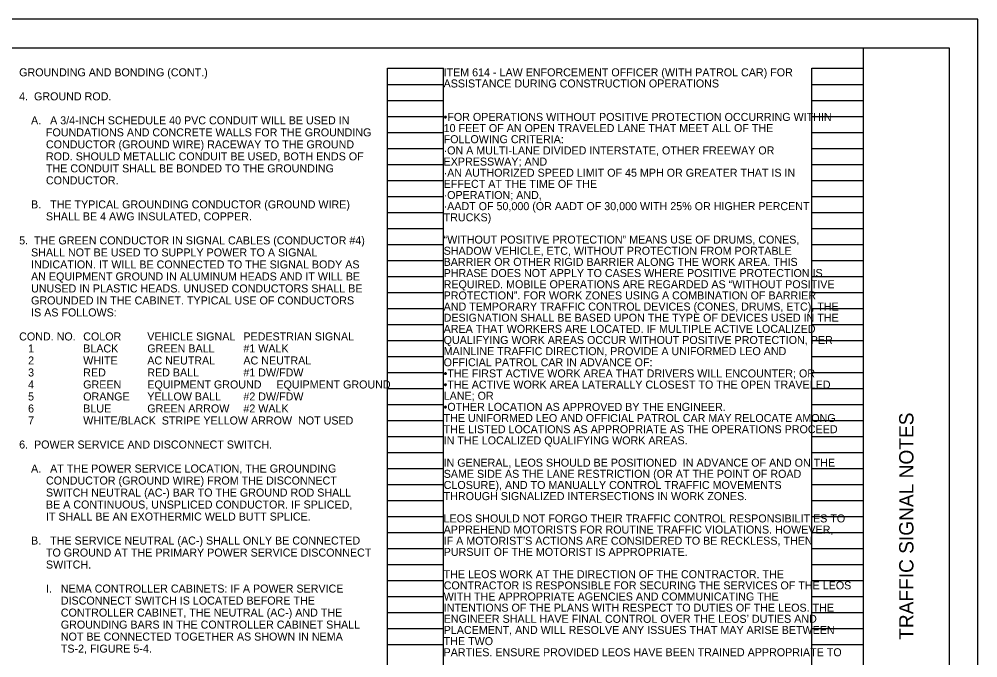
# Model space of a CAD drawing. Extents: x 0 to 34, y 0 to 22.
# Drawn here: x 17.24 to 34, y 10.83 to 22 of the extents above; entities that cross this region are included whole.
import ezdxf

# ---------------------------------------------------------------- set-up
doc = ezdxf.new("R2010")
doc.units = 0
for name, color, linetype in [('SH_Border', 7, 'Continuous'), ('SH_Cut_Line', 7, 'Continuous'), ('SH_Data', 7, 'Continuous'), ('SH_Text', 7, 'Continuous')]:
    doc.layers.add(name, color=color, linetype=linetype)

msp = doc.modelspace()

# ---------------------------------------------------------------- linework, layer by layer
at = {"layer": 'SH_Border'}
msp.add_line((32, 0.5), (32, 21.5), dxfattribs=at)
msp.add_lwpolyline([(1.5, 21.5), (33.5, 21.5), (33.5, 0.5), (1.5, 0.5)], close=True, dxfattribs=at)
at = {"layer": 'SH_Cut_Line'}
msp.add_lwpolyline([(0, 0), (34, 0), (34, 22), (0, 22)], close=True, dxfattribs=at)
at = {"layer": 'SH_Data'}
for p, q in [((23.68, 0.98), (23.68, 21.14)), ((23.68, 21.14), (24.66, 21.14)), ((24.66, 0.98), (24.66, 21.14)), ((31.1, 0.98), (31.1, 21.14)), ((31.1, 21.14), (32, 21.14)), ((32, 0.98), (32, 21.14)), ((23.68, 20.86), (24.66, 20.86)), ((31.1, 20.86), (32, 20.86)), ((23.68, 20.58), (24.66, 20.58)), ((31.1, 20.58), (32, 20.58)), ((23.68, 20.3), (24.66, 20.3)), ((31.1, 20.3), (32, 20.3)), ((23.68, 20.02), (24.66, 20.02)), ((31.1, 20.02), (32, 20.02)), ((23.68, 19.74), (24.66, 19.74)), ((31.1, 19.74), (32, 19.74)), ((23.68, 19.46), (24.66, 19.46)), ((31.1, 19.46), (32, 19.46)), ((23.68, 19.18), (24.66, 19.18)), ((31.1, 19.18), (32, 19.18)), ((23.68, 18.9), (24.66, 18.9)), ((31.1, 18.9), (32, 18.9)), ((23.68, 18.62), (24.66, 18.62)), ((31.1, 18.62), (32, 18.62)), ((23.68, 18.34), (24.66, 18.34)), ((31.1, 18.34), (32, 18.34)), ((23.68, 18.06), (24.66, 18.06)), ((31.1, 18.06), (32, 18.06)), ((23.68, 17.78), (24.66, 17.78)), ((31.1, 17.78), (32, 17.78)), ((23.68, 17.5), (24.66, 17.5)), ((31.1, 17.5), (32, 17.5)), ((23.68, 17.22), (24.66, 17.22)), ((31.1, 17.22), (32, 17.22)), ((23.68, 16.94), (24.66, 16.94)), ((31.1, 16.94), (32, 16.94)), ((23.68, 16.66), (24.66, 16.66)), ((31.1, 16.66), (32, 16.66)), ((23.68, 16.38), (24.66, 16.38)), ((31.1, 16.38), (32, 16.38)), ((23.68, 16.1), (24.66, 16.1)), ((31.1, 16.1), (32, 16.1)), ((23.68, 15.82), (24.66, 15.82)), ((31.1, 15.82), (32, 15.82)), ((23.68, 15.54), (24.66, 15.54)), ((31.1, 15.54), (32, 15.54)), ((23.68, 15.26), (24.66, 15.26)), ((31.1, 15.26), (32, 15.26)), ((23.68, 14.98), (24.66, 14.98)), ((31.1, 14.98), (32, 14.98)), ((23.68, 14.7), (24.66, 14.7)), ((31.1, 14.7), (32, 14.7)), ((23.68, 14.42), (24.66, 14.42)), ((31.1, 14.42), (32, 14.42)), ((23.68, 14.14), (24.66, 14.14)), ((31.1, 14.14), (32, 14.14)), ((23.68, 13.86), (24.66, 13.86)), ((31.1, 13.86), (32, 13.86)), ((23.68, 13.58), (24.66, 13.58)), ((31.1, 13.58), (32, 13.58)), ((23.68, 13.3), (24.66, 13.3)), ((31.1, 13.3), (32, 13.3)), ((23.68, 13.02), (24.66, 13.02)), ((31.1, 13.02), (32, 13.02)), ((23.68, 12.74), (24.66, 12.74)), ((31.1, 12.74), (32, 12.74)), ((23.68, 12.46), (24.66, 12.46)), ((31.1, 12.46), (32, 12.46)), ((23.68, 12.18), (24.66, 12.18)), ((31.1, 12.18), (32, 12.18)), ((23.68, 11.9), (24.66, 11.9)), ((31.1, 11.9), (32, 11.9)), ((23.68, 11.62), (24.66, 11.62)), ((31.1, 11.62), (32, 11.62)), ((23.68, 11.34), (24.66, 11.34)), ((31.1, 11.34), (32, 11.34)), ((23.68, 11.06), (24.66, 11.06)), ((31.1, 11.06), (32, 11.06))]:
    msp.add_line(p, q, dxfattribs=at)

# ---------------------------------------------------------------- texts
msp.add_text('TRAFFIC SIGNAL NOTES', height=0.25, rotation=90, dxfattribs=at).set_placement((32.875, 11.144))
at = {"layer": 'SH_Text'}
for s, p in [('GROUNDING AND BONDING (CONT.)', (17.24, 21)), ('ITEM 614 - LAW ENFORCEMENT OFFICER (WITH PATROL CAR) FOR ', (24.66, 21)), ('ASSISTANCE DURING CONSTRUCTION OPERATIONS', (24.66, 20.805)), ('4.  GROUND ROD.', (17.24, 20.58)), ('    A.   A 3/4-INCH SCHEDULE 40 PVC CONDUIT WILL BE USED IN', (17.24, 20.16)), ('•FOR OPERATIONS WITHOUT POSITIVE PROTECTION OCCURRING WITHIN ', (24.66, 20.22)), ('10 FEET OF AN OPEN TRAVELED LANE THAT MEET ALL OF THE ', (24.661, 20.025)), ('         FOUNDATIONS AND CONCRETE WALLS FOR THE GROUNDING', (17.24, 19.95)), ('FOLLOWING CRITERIA:', (24.661, 19.83)), ('         CONDUCTOR (GROUND WIRE) RACEWAY TO THE GROUND', (17.24, 19.74)), ('         ROD. SHOULD METALLIC CONDUIT BE USED, BOTH ENDS OF', (17.24, 19.53)), ('·ON A MULTI-LANE DIVIDED INTERSTATE, OTHER FREEWAY OR ', (24.66, 19.634)), ('         THE CONDUIT SHALL BE BONDED TO THE GROUNDING', (17.24, 19.32)), ('EXPRESSWAY; AND', (24.66, 19.439)), ('·AN AUTHORIZED SPEED LIMIT OF 45 MPH OR GREATER THAT IS IN ', (24.66, 19.244)), ('         CONDUCTOR.', (17.24, 19.11)), ('EFFECT AT THE TIME OF THE', (24.661, 19.049)), ('·OPERATION; AND,', (24.66, 18.854)), ('    B.   THE TYPICAL GROUNDING CONDUCTOR (GROUND WIRE)', (17.24, 18.69)), ('·AADT OF 50,000 (OR AADT OF 30,000 WITH 25% OR HIGHER PERCENT ', (24.66, 18.659)), ('         SHALL BE 4 AWG INSULATED, COPPER.', (17.24, 18.48)), ('TRUCKS)', (24.661, 18.464)), ('5.  THE GREEN CONDUCTOR IN SIGNAL CABLES (CONDUCTOR #4)', (17.24, 18.06)), ('“WITHOUT POSITIVE PROTECTION” MEANS USE OF DRUMS, CONES, ', (24.66, 18.074)), ('    SHALL NOT BE USED TO SUPPLY POWER TO A SIGNAL', (17.24, 17.85)), ('SHADOW VEHICLE, ETC, WITHOUT PROTECTION FROM PORTABLE ', (24.661, 17.879)), ('    INDICATION. IT WILL BE CONNECTED TO THE SIGNAL BODY AS', (17.24, 17.64)), ('BARRIER OR OTHER RIGID BARRIER ALONG THE WORK AREA. THIS ', (24.661, 17.684)), ('PHRASE DOES NOT APPLY TO CASES WHERE POSITIVE PROTECTION IS ', (24.661, 17.489)), ('    AN EQUIPMENT GROUND IN ALUMINUM HEADS AND IT WILL BE', (17.24, 17.43)), ('REQUIRED. MOBILE OPERATIONS ARE REGARDED AS “WITHOUT POSITIVE ', (24.661, 17.293)), ('    UNUSED IN PLASTIC HEADS. UNUSED CONDUCTORS SHALL BE', (17.24, 17.22)), ('    GROUNDED IN THE CABINET. TYPICAL USE OF CONDUCTORS', (17.24, 17.01)), ('PROTECTION”. FOR WORK ZONES USING A COMBINATION OF BARRIER ', (24.661, 17.098)), ('    IS AS FOLLOWS:', (17.24, 16.8)), ('AND TEMPORARY TRAFFIC CONTROL DEVICES (CONES, DRUMS, ETC), THE ', (24.661, 16.903)), ('DESIGNATION SHALL BE BASED UPON THE TYPE OF DEVICES USED IN THE ', (24.661, 16.708)), ('AREA THAT WORKERS ARE LOCATED. IF MULTIPLE ACTIVE LOCALIZED ', (24.661, 16.513)), ('COND. NO.', (17.24, 16.38)), ('COLOR', (18.36, 16.38)), ('VEHICLE SIGNAL', (19.48, 16.38)), ('PEDESTRIAN SIGNAL', (21.16, 16.38)), ('QUALIFYING WORK AREAS OCCUR WITHOUT POSITIVE PROTECTION, PER ', (24.661, 16.318)), ('   1         ', (17.24, 16.17)), ('BLACK        ', (18.36, 16.17)), ('GREEN BALL      ', (19.48, 16.17)), ('#1 WALK', (21.16, 16.17)), ('MAINLINE TRAFFIC DIRECTION, PROVIDE A UNIFORMED LEO AND ', (24.661, 16.123)), ('   2         ', (17.24, 15.96)), ('WHITE        ', (18.36, 15.96)), ('AC NEUTRAL     ', (19.48, 15.96)), ('AC NEUTRAL', (21.16, 15.96)), ('OFFICIAL PATROL CAR IN ADVANCE OF:', (24.661, 15.928)), ('   3         ', (17.24, 15.75)), ('RED          ', (18.36, 15.75)), ('RED BALL         ', (19.48, 15.75)), ('#1 DW/FDW', (21.16, 15.75)), ('•THE FIRST ACTIVE WORK AREA THAT DRIVERS WILL ENCOUNTER; OR', (24.66, 15.733)), ('   4         ', (17.24, 15.54)), ('GREEN        ', (18.36, 15.54)), ('EQUIPMENT GROUND     EQUIPMENT GROUND', (19.48, 15.54)), ('•THE ACTIVE WORK AREA LATERALLY CLOSEST TO THE OPEN TRAVELED ', (24.66, 15.538)), ('   5         ', (17.24, 15.33)), ('ORANGE   ', (18.36, 15.33)), ('YELLOW BALL      ', (19.48, 15.33)), ('#2 DW/FDW', (21.16, 15.33)), ('LANE; OR', (24.662, 15.343)), ('   6         ', (17.24, 15.12)), ('BLUE         ', (18.36, 15.12)), ('GREEN ARROW    ', (19.48, 15.12)), ('#2 WALK', (21.16, 15.12)), ('•OTHER LOCATION AS APPROVED BY THE ENGINEER.', (24.66, 15.148)), ('THE UNIFORMED LEO AND OFFICIAL PATROL CAR MAY RELOCATE AMONG ', (24.66, 14.953)), ('   7         ', (17.24, 14.91)), ('WHITE/BLACK  STRIPE YELLOW ARROW  NOT USED', (18.36, 14.91)), ('THE LISTED LOCATIONS AS APPROPRIATE AS THE OPERATIONS PROCEED ', (24.662, 14.757)), ('6.  POWER SERVICE AND DISCONNECT SWITCH.', (17.24, 14.49)), ('IN THE LOCALIZED QUALIFYING WORK AREAS.', (24.662, 14.562)), ('IN GENERAL, LEOS SHOULD BE POSITIONED  IN ADVANCE OF AND ON THE ', (24.66, 14.172)), ('    A.   AT THE POWER SERVICE LOCATION, THE GROUNDING', (17.24, 14.07)), ('SAME SIDE AS THE LANE RESTRICTION (OR AT THE POINT OF ROAD ', (24.662, 13.977)), ('         CONDUCTOR (GROUND WIRE) FROM THE DISCONNECT', (17.24, 13.86)), ('CLOSURE), AND TO MANUALLY CONTROL TRAFFIC MOVEMENTS ', (24.662, 13.782)), ('         SWITCH NEUTRAL (AC-) BAR TO THE GROUND ROD SHALL', (17.24, 13.65)), ('         BE A CONTINUOUS, UNSPLICED CONDUCTOR. IF SPLICED,', (17.24, 13.44)), ('THROUGH SIGNALIZED INTERSECTIONS IN WORK ZONES.', (24.662, 13.587)), ('         IT SHALL BE AN EXOTHERMIC WELD BUTT SPLICE.', (17.24, 13.23)), ('LEOS SHOULD NOT FORGO THEIR TRAFFIC CONTROL RESPONSIBILITIES TO ', (24.66, 13.197)), ('APPREHEND MOTORISTS FOR ROUTINE TRAFFIC VIOLATIONS. HOWEVER, ', (24.662, 13.002)), ('    B.   THE SERVICE NEUTRAL (AC-) SHALL ONLY BE CONNECTED', (17.24, 12.81)), ('IF A MOTORIST’S ACTIONS ARE CONSIDERED TO BE RECKLESS, THEN ', (24.662, 12.807)), ('         TO GROUND AT THE PRIMARY POWER SERVICE DISCONNECT', (17.24, 12.6)), ('PURSUIT OF THE MOTORIST IS APPROPRIATE.', (24.662, 12.612)), ('         SWITCH.', (17.24, 12.39)), ('THE LEOS WORK AT THE DIRECTION OF THE CONTRACTOR. THE ', (24.66, 12.221)), ('         I.   NEMA CONTROLLER CABINETS: IF A POWER SERVICE', (17.24, 11.97)), ('CONTRACTOR IS RESPONSIBLE FOR SECURING THE SERVICES OF THE LEOS ', (24.662, 12.026)), ('              DISCONNECT SWITCH IS LOCATED BEFORE THE', (17.24, 11.76)), ('WITH THE APPROPRIATE AGENCIES AND COMMUNICATING THE ', (24.662, 11.831)), ('INTENTIONS OF THE PLANS WITH RESPECT TO DUTIES OF THE LEOS. THE ', (24.662, 11.636)), ('              CONTROLLER CABINET, THE NEUTRAL (AC-) AND THE', (17.24, 11.55)), ('ENGINEER SHALL HAVE FINAL CONTROL OVER THE LEOS’ DUTIES AND ', (24.662, 11.441)), ('              GROUNDING BARS IN THE CONTROLLER CABINET SHALL', (17.24, 11.34)), ('              NOT BE CONNECTED TOGETHER AS SHOWN IN NEMA', (17.24, 11.13)), ('PLACEMENT, AND WILL RESOLVE ANY ISSUES THAT MAY ARISE BETWEEN ', (24.662, 11.246)), ('              TS-2, FIGURE 5-4.', (17.24, 10.92)), ('THE TWO', (24.662, 11.051)), ('PARTIES. ENSURE PROVIDED LEOS HAVE BEEN TRAINED APPROPRIATE TO ', (24.66, 10.856))]:
    msp.add_text(s, height=0.14, dxfattribs=at).set_placement(p)

doc.saveas('drawing.dxf')
